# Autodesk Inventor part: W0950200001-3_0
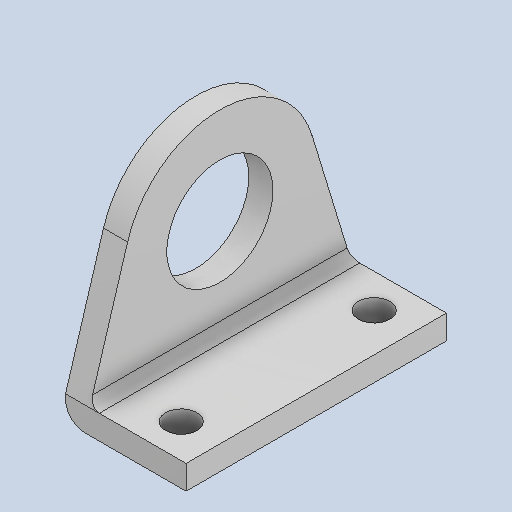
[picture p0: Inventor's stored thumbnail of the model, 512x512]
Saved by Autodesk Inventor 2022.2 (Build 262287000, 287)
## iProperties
Created: 2024-10
Part Number: W0950200001-3_0
Material: Generico
Document SubType Name: Modeling
Designer: 18907419
Density: 1 g/cm^3
Appearance: Default
Author: 18907419
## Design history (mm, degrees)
feature "Solid1"
node "Solido1"
